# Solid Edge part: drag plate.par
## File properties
Author: Deepak Maini
Template: Normal.par
Last saved by: Robert a Rhodes jr
Revision: 6
Application: Solid Edge
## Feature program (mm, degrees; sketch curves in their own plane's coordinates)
sketch for "unnamed Protrusion 1" plane through (0, 0, 0) normal (1, 0, 0) x-axis (0, 1, 0)
  line (-15, 45) -> (-15, -45)
  line (-15, -45) -> (15, -45)
  line (15, -45) -> (15, 30)
  arc centre (0, 30) radius 15 from (0, 45) to (15, 30) cw
  line (0, 45) -> (-15, 45)
extrude "unnamed Protrusion 1" add finite 66 symmetric
sketch for "unnamed Cutout 1" plane through (0, -15, 0) normal (0, -1, 0) x-axis (1, 0, 0)
  arc centre (0, 70) radius 115 from (-33, -40.1635) to (33, -40.1635) ccw
  line (33, -55.08) -> (33, -40.1635)
  line (-33, -55.08) -> (33, -55.08)
  line (-33, -40.1635) -> (-33, -55.08)
extrude "unnamed Cutout 1" cut through along -normal
sketch for "unnamed Hole 1" plane through (33, 0, 2.4182) normal (1, 0, 0) x-axis (0, 1, 0)
  hole centre (0, 27.5818) bore radius 7
hole "unnamed Hole 1" finite
sketch for "unnamed Hole 2" plane through (0, -15, 0) normal (0, -1, 0) x-axis (1, 0, 0)
  hole centre (0, -10) bore radius 12
hole "unnamed Hole 2" through
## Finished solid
Body 1: solid body, 11 faces, 21 edges, 10 vertices.
  Faces by surface: plane 6, cylinder 4, cone 1
  Edges by curve: line 11, circle 10
Bounding box of the edges (mm): 66.000 x 30.000 x 90.000, from (-33, -15, -45) to (33, 15, 45).
Cylindrical faces by radius (mm): R12 x1, R15 x2, R115 x1
Conical faces (half-angle, radius in mm at the cone's reference point): 1.1458 deg R7 x1
Planar faces by outward normal: +x 1, +y 1, +z 1, -x 1, -y 2
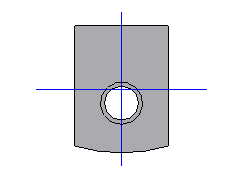
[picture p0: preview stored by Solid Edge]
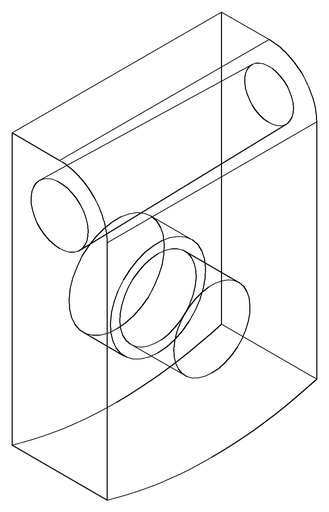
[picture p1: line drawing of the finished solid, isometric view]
